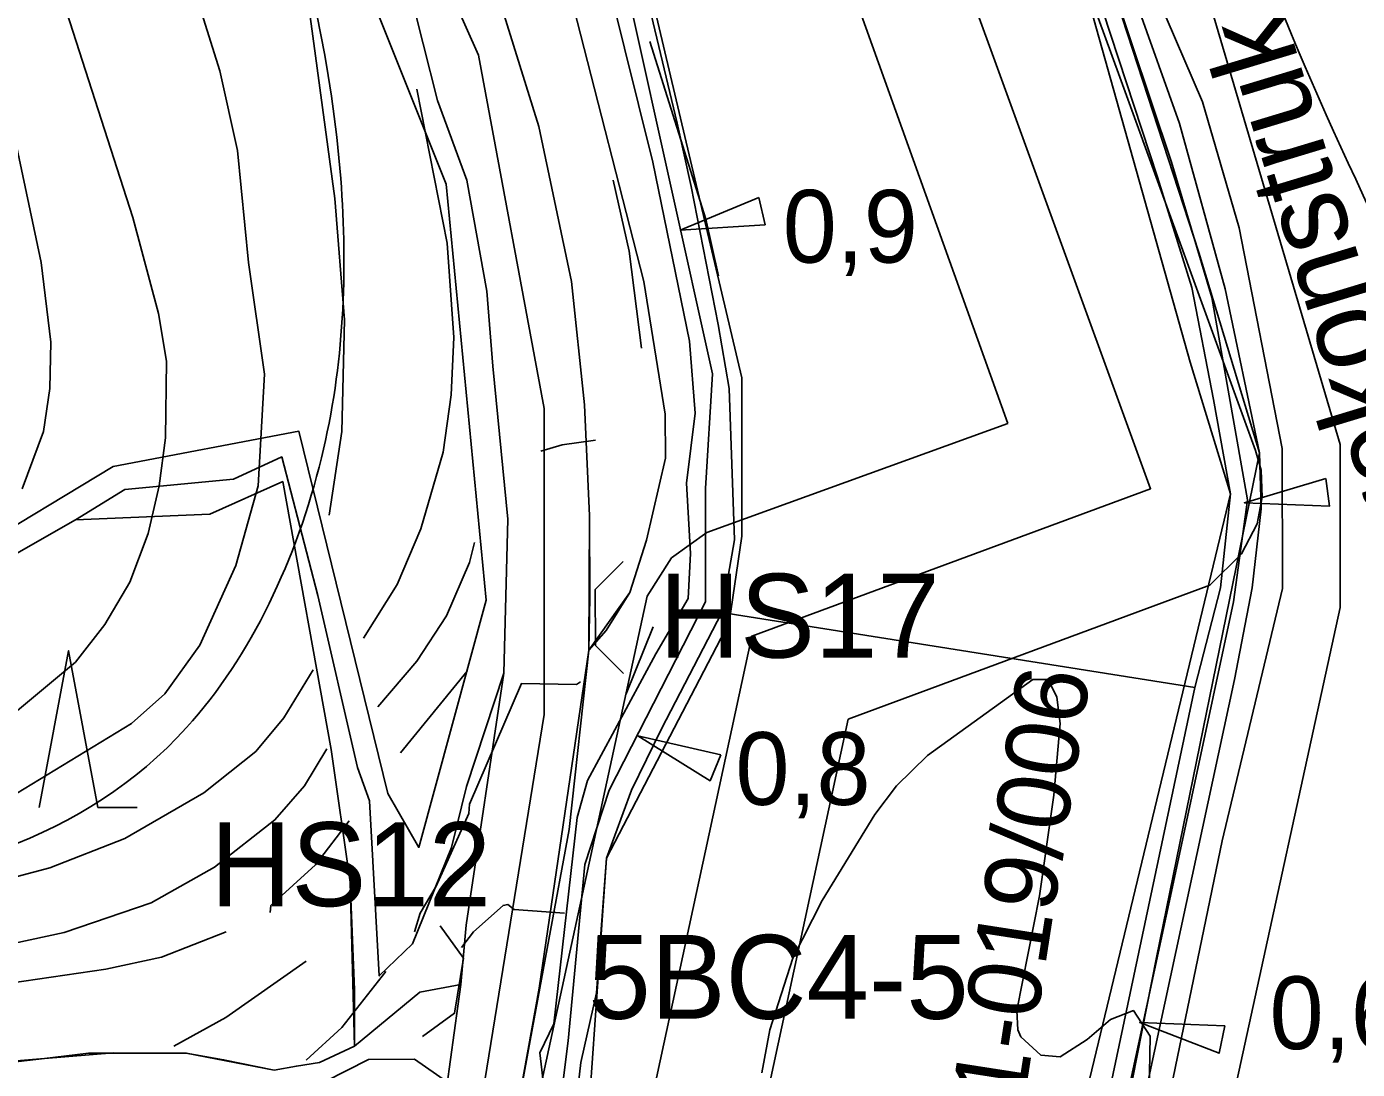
# Model space of a CAD drawing. Extents: x -684583 to -680383, y -1157874 to -1154904.
# Drawn here: x -683125.8 to -682887.9, y -1157689.5 to -1157503 of the extents above; entities that cross this region are included whole.
import ezdxf

# ---------------------------------------------------------------- set-up
doc = ezdxf.new("R2010")
doc.units = 0
for name, color, linetype in [('01_DOPRAVA', 7, 'Continuous'), ('01_OBVOD PÚ', 7, 'Continuous'), ('01_PRVKY PRŮZKUMU', 7, 'Continuous'), ('01_PRVKY PSZ', 7, 'Continuous'), ('01_SPRÁV_HRANICE', 7, 'Continuous'), ('01_VRSTEVNICE', 7, 'Continuous'), ('02_KULTURY STAV', 7, 'Continuous'), ('03_PC_OBJEKTY_STAV', 7, 'Continuous'), ('03_PC_STAV', 7, 'Continuous'), ('04_ZPF_OP_ORGAN', 7, 'Continuous'), ('05_VHO_V_TOK', 7, 'Continuous'), ('06_BIOGEOGRAFIE', 7, 'Continuous'), ('06_ÚSES_BC', 7, 'Continuous'), ('06_ÚSES_IP', 7, 'Continuous'), ('07_OCH_P A POPISY TI', 7, 'Continuous'), ('07_PLYNOVOD', 7, 'Continuous')]:
    doc.layers.add(name, color=color, linetype=linetype)

msp = doc.modelspace()

# ---------------------------------------------------------------- linework, layer by layer
at = {"layer": '01_DOPRAVA'}
msp.add_lwpolyline([(-683054.51, -1157758.92), (-683045.66, -1157702.14), (-683033.32, -1157625.99), (-683033.32, -1157571.3), (-683045.07, -1157508.09), (-683105.62, -1157372.25), (-683148.82, -1157294.04), (-683163.81, -1157254.05), (-683168.81, -1157196.71), (-683165.28, -1157159.67), (-683135.89, -1157075.28), (-683079.46, -1156981.49), (-683035.96, -1156902.98), (-682993.94, -1156817.72), (-682972.78, -1156716.87), (-682952.5, -1156631.31), (-682921.05, -1156497.23), (-682883.43, -1156372.57), (-682870.79, -1156344.34), (-682802.61, -1156200.56), (-682782.62, -1156147.93)], dxfattribs=at)
at = {"layer": '01_OBVOD PÚ'}
msp.add_lwpolyline([(-682865.53, -1157341.29), (-682893.56, -1157332.68), (-682915.26, -1157330.93), (-682949.07, -1157325.62), (-682955.11, -1157345.57), (-682959.54, -1157356.74), (-682962.28, -1157384.25), (-682960.41, -1157397.25), (-682935.1, -1157471.19), (-682915.62, -1157516.47), (-682909.09, -1157538.97), (-682901.39, -1157578.47), (-682901.33, -1157603.49), (-682912.12, -1157648.58), (-682925.59, -1157713.72), (-682932.97, -1157763.18), (-682930, -1157800.25), (-682921.17, -1157813.46), (-682989.26, -1157839.49)], dxfattribs=at)
at = {"layer": '01_PRVKY PRŮZKUMU'}
for points in [[(-683025.92, -1157705.32), (-683022.15, -1157651.71), (-683000.24, -1157609.57), (-682997.99, -1157594.15), (-682997.99, -1157565.8), (-683020.17, -1157471.89), (-683050.97, -1157393.39), (-683079.01, -1157360), (-683101.29, -1157316.95)], [(-682879.89, -1157360.72), (-682946.46, -1157363.51), (-682949.54, -1157394.01), (-682938.25, -1157436.4), (-682914.65, -1157497.57), (-682890.98, -1157577.72), (-682890.98, -1157606.89), (-682909.88, -1157693.41)]]:
    msp.add_lwpolyline(points, dxfattribs=at)
at = {"layer": '01_PRVKY PSZ'}
msp.add_lwpolyline([(-682951.59, -1157030.23), (-682949.58, -1157052.3), (-682959.2, -1157265.52), (-682962.61, -1157285.78), (-682967.05, -1157374.21), (-682960.06, -1157422.81), (-682935.41, -1157484.7), (-682916.27, -1157543.42), (-682905.44, -1157579.25), (-682923.84, -1157669.47), (-682932.49, -1157713.29), (-682940.15, -1157759.63), (-682931.41, -1157813.92)], dxfattribs=at)
at = {"layer": '01_SPRÁV_HRANICE'}
msp.add_lwpolyline([(-682865.53, -1157341.29), (-682893.56, -1157332.68), (-682915.26, -1157330.93), (-682949.07, -1157325.62), (-682955.11, -1157345.57), (-682959.54, -1157356.74), (-682962.28, -1157384.25), (-682960.41, -1157397.25), (-682935.1, -1157471.19), (-682915.62, -1157516.47), (-682909.09, -1157538.97), (-682901.39, -1157578.47), (-682901.33, -1157603.49), (-682912.12, -1157648.58), (-682925.59, -1157713.72), (-682932.97, -1157763.18), (-682930, -1157800.25), (-682921.17, -1157813.46), (-682989.26, -1157839.49)], dxfattribs=at)
at = {"layer": '01_VRSTEVNICE'}
for points in [[(-683136.36, -1157347.17), (-683133.65, -1157353.16), (-683120.24, -1157376.84), (-683111.97, -1157392.82), (-683097.42, -1157424.77), (-683087.72, -1157450.73), (-683080.59, -1157475.55), (-683075.17, -1157501.23), (-683070.74, -1157533.75), (-683069.03, -1157555.43), (-683069.46, -1157575.4), (-683071.74, -1157590.38)], [(-683127.66, -1157640.16), (-683107.12, -1157627.61), (-683101.13, -1157622.33), (-683094.85, -1157613.63), (-683088.43, -1157599.37), (-683084.44, -1157585.1), (-683083.3, -1157565.13), (-683086.15, -1157545.16), (-683088.15, -1157525.19), (-683091.29, -1157510.93), (-683094.85, -1157499.52), (-683102.98, -1157479.54), (-683118.1, -1157436.75), (-683128.94, -1157409.08)], [(-683127.8, -1157625.61), (-683117.1, -1157616.63), (-683111.83, -1157609.92), (-683107.41, -1157602.36), (-683104.12, -1157593.66), (-683102.13, -1157585.1), (-683100.99, -1157576.54), (-683100.84, -1157562.85), (-683102.27, -1157554.29), (-683106.83, -1157537.17), (-683119.24, -1157498.66), (-683131.37, -1157455.87)], [(-683014.4, -1157505.65), (-683004.42, -1157537.46), (-683002.13, -1157547.59)], [(-683056.05, -1157514.21), (-683050.63, -1157541.74), (-683049.49, -1157558.57), (-683049.92, -1157568.84), (-683051.35, -1157579.11), (-683055.34, -1157592.8), (-683059.62, -1157602.79), (-683065.61, -1157612.35)], [(-683128.09, -1157522.34), (-683123.24, -1157545.16), (-683121.53, -1157559.43), (-683121.67, -1157567.7), (-683122.81, -1157575.4), (-683126.66, -1157585.67)], [(-683015.9, -1157560.51), (-683018.11, -1157543.16), (-683020.96, -1157530.47)], [(-683033.91, -1157578.93), (-683030.1, -1157577.8), (-683024.13, -1157576.98)], [(-683045.78, -1157595.23), (-683046.64, -1157598.8), (-683050.78, -1157608.35), (-683056.05, -1157616.48), (-683063.04, -1157624.61)], [(-683013.83, -1157610.35), (-683018.68, -1157622.33)], [(-683159.47, -1157661.56), (-683142.21, -1157658.85), (-683121.67, -1157653.43), (-683108.26, -1157648.15), (-683094.14, -1157640.02), (-683084.87, -1157632.6), (-683079.87, -1157626.59), (-683074.6, -1157618.05)], [(-683059.01, -1157632.86), (-683047.07, -1157618.25)], [(-683056.48, -1157664.84), (-683055.48, -1157661.56), (-683052.63, -1157656.71), (-683046.78, -1157643.73), (-683046.64, -1157642.02), (-683037.37, -1157620.48), (-683027.52, -1157620.62), (-683026.81, -1157620.19)], [(-682925.52, -1157713.39), (-682924.96, -1157683.53), (-682927.96, -1157678.96), (-682932.09, -1157680.53), (-682936.23, -1157684.1), (-682941.08, -1157687.23), (-682944.5, -1157686.95), (-682948.07, -1157683.67), (-682948.64, -1157682.38), (-682948.79, -1157678.96), (-682944.79, -1157658.42), (-682942.22, -1157640.45), (-682941.08, -1157627.61), (-682941.65, -1157622.9), (-682943.22, -1157619.76), (-682945.93, -1157619.76), (-682964.76, -1157633.32), (-682970.32, -1157638.74), (-682974.17, -1157643.87), (-682983.59, -1157659.28), (-682988.87, -1157669.55), (-682993, -1157682.38), (-682994.43, -1157690.09)], [(-683337.78, -1157704.35), (-683318.09, -1157695.65), (-683309.1, -1157692.8), (-683302.26, -1157691.37), (-683282.57, -1157689.38), (-683275.44, -1157689.52), (-683240.92, -1157686.09), (-683219.52, -1157681.81), (-683210.68, -1157679.25), (-683179.87, -1157672.26), (-683171.17, -1157671.12), (-683145.35, -1157669.4), (-683128.23, -1157666.98), (-683119.1, -1157664.98), (-683103.55, -1157659.71), (-683092.28, -1157653.28), (-683081.44, -1157644.87), (-683076.17, -1157638.74), (-683072.17, -1157632.17)], [(-683082.3, -1157661.42), (-683082.16, -1157660.13), (-683074.17, -1157652.86), (-683068.18, -1157645.01)], [(-683029.66, -1157661.56), (-683038.65, -1157660.85), (-683039.79, -1157659.99), (-683040.65, -1157660.13), (-683045.92, -1157664.84), (-683048.07, -1157667.69)], [(-683224.66, -1157694.51), (-683216.67, -1157691.23), (-683180.15, -1157681.53), (-683111.68, -1157671.54), (-683101.7, -1157669.4), (-683090.15, -1157664.84)], [(-683099.5, -1157685.31), (-683090.24, -1157680.17), (-683075.88, -1157670.12)], [(-683061.62, -1157671.97), (-683069.46, -1157681.96), (-683075.88, -1157687.81)]]:
    msp.add_lwpolyline(points, dxfattribs=at)
at = {"layer": '02_KULTURY STAV'}
for points in [[(-683033.42, -1157692.12), (-683034.08, -1157686.53), (-683031.58, -1157681.33), (-683027.44, -1157644.4), (-683025.58, -1157637.78), (-683013.37, -1157615.15), (-683007.58, -1157605.24), (-683007.18, -1157597.21), (-683007.87, -1157584.65), (-683006.31, -1157572.11), (-683007.34, -1157559.25), (-683013.9, -1157527.23), (-683021.51, -1157496.5), (-683027.43, -1157474.84), (-683031.55, -1157461.02), (-683044.3, -1157425.6), (-683054.13, -1157403.28), (-683058.47, -1157396.94), (-683070.54, -1157382.77), (-683080.89, -1157368.49), (-683092.7, -1157351.15), (-683100.09, -1157338.35), (-683104.91, -1157328.42), (-683109.86, -1157316.49)], [(-683123.39, -1157320.54), (-683093.3, -1157375.73), (-683088.54, -1157377.96), (-683076.17, -1157387.28), (-683062.38, -1157405.88), (-683055.9, -1157423.11), (-683052.29, -1157436.79), (-683041.28, -1157465.46), (-683028.05, -1157499.48), (-683015.51, -1157548.59), (-683011.68, -1157572.3), (-683011.64, -1157580.2), (-683015.05, -1157594.84), (-683018, -1157604.18), (-683025.32, -1157614.52), (-683034.2, -1157674.95), (-683041.64, -1157716.25)], [(-682925.59, -1157713.72), (-682912.12, -1157648.58), (-682901.33, -1157603.49), (-682901.39, -1157578.47), (-682909.09, -1157538.97), (-682915.62, -1157516.47), (-682935.1, -1157471.19)], [(-683016.79, -1157489.83), (-683009.51, -1157520.25), (-683007.03, -1157531.61), (-683002.19, -1157556.27), (-683000.27, -1157567.73), (-682999.3, -1157594.75), (-683001.56, -1157607.79), (-683012.36, -1157628.56), (-683017.73, -1157639.54), (-683022.15, -1157651.71), (-683023.59, -1157670.76), (-683023.97, -1157675.79), (-683026.76, -1157688.24), (-683028.56, -1157703.91)], [(-683052.69, -1157706.77), (-683048.74, -1157678.14), (-683048.22, -1157674.26), (-683047.26, -1157663.68), (-683040.52, -1157618.63), (-683039.8, -1157591.06), (-683042.49, -1157563.72), (-683043.54, -1157550.33), (-683047.17, -1157530.46), (-683052.37, -1157516.21), (-683057.49, -1157495.91), (-683043.34, -1157491.71), (-683034.27, -1157520.87), (-683028.44, -1157548.59), (-683026.1, -1157570.61), (-683025.21, -1157590.49), (-683025.32, -1157614.52), (-683034.2, -1157674.95), (-683041.64, -1157716.25)], [(-683033.42, -1157692.12), (-683034.08, -1157686.53), (-683031.58, -1157681.33), (-683027.44, -1157644.4), (-683025.58, -1157637.78), (-683013.37, -1157615.15), (-683007.58, -1157605.24), (-683007.18, -1157597.21), (-683007.87, -1157584.65), (-683006.31, -1157572.11), (-683007.34, -1157559.25), (-683013.9, -1157527.23), (-683021.51, -1157496.5)], [(-682927.4, -1157498.74), (-682919.76, -1157520.36), (-682911.54, -1157549.91), (-682905.44, -1157579.25), (-682905.14, -1157589.23), (-682906.77, -1157603.34), (-682909.9, -1157619.72), (-682927.09, -1157699.5)], [(-682927.09, -1157699.5), (-682909.9, -1157619.72), (-682906.77, -1157603.34), (-682905.14, -1157589.23), (-682905.44, -1157579.25), (-682911.54, -1157549.91), (-682919.76, -1157520.36), (-682927.4, -1157498.74)], [(-682933.41, -1157500.16), (-682923.67, -1157529.91), (-682917.54, -1157549.63), (-682913.64, -1157569.71), (-682910.6, -1157586.57), (-682912.42, -1157603.36), (-682917.01, -1157621.2), (-682932.27, -1157693.31)], [(-683128.09, -1157597.48), (-683117.09, -1157591.23), (-683093.1, -1157590.19), (-683080.04, -1157584.35), (-683071.41, -1157632.26), (-683067.97, -1157656), (-683067.24, -1157685.33), (-683073.47, -1157688.22), (-683077.6, -1157688.87), (-683081.6, -1157689.6), (-683090.63, -1157687.74), (-683097.29, -1157686.54), (-683114.77, -1157686.54), (-683122.62, -1157687.52), (-683133.39, -1157688.42)], [(-682932.27, -1157693.31), (-682917.01, -1157621.2), (-683001.56, -1157607.79), (-683012.36, -1157628.56), (-683017.73, -1157639.54), (-683022.15, -1157651.71), (-683023.59, -1157670.76), (-683023.97, -1157675.79), (-683026.76, -1157688.24), (-683028.56, -1157703.91)], [(-683123.59, -1157642.62), (-683118.34, -1157614.62), (-683113.09, -1157642.62), (-683106.09, -1157642.62)], [(-683155.61, -1157697), (-683139.21, -1157689.44), (-683122.62, -1157687.52), (-683110.28, -1157686.5), (-683097.29, -1157686.54), (-683081.6, -1157689.6), (-683077.6, -1157688.87), (-683073.47, -1157688.22), (-683067.24, -1157685.33), (-683055.55, -1157675.64), (-683048.22, -1157674.26), (-683048.74, -1157678.14), (-683052.69, -1157706.77)]]:
    msp.add_lwpolyline(points, dxfattribs=at)
for points in [[(-683050.32, -1157398.08), (-683047.27, -1157404.35), (-683041.25, -1157416.74), (-683026.4, -1157458.67), (-683016.79, -1157489.83), (-683009.51, -1157520.25), (-683007.03, -1157531.61), (-683002.19, -1157556.27), (-683000.27, -1157567.73), (-682999.3, -1157594.75), (-683001.56, -1157607.79), (-682917.01, -1157621.2), (-682912.42, -1157603.36), (-682910.6, -1157586.57), (-682913.64, -1157569.71), (-682917.54, -1157549.63), (-682923.67, -1157529.91), (-682933.41, -1157500.16), (-682952.33, -1157451.75), (-682962.44, -1157424.45), (-682967.7, -1157402.05), (-682969.62, -1157390.02), (-682970.5, -1157367.3)], [(-683093.3, -1157375.73), (-683088.54, -1157377.96), (-683076.17, -1157387.28), (-683062.38, -1157405.88), (-683055.9, -1157423.11), (-683052.29, -1157436.79), (-683041.28, -1157465.46), (-683028.05, -1157499.48), (-683015.51, -1157548.59), (-683011.68, -1157572.3), (-683011.64, -1157580.2), (-683015.05, -1157594.84), (-683018, -1157604.18), (-683022.23, -1157611), (-683025.32, -1157614.52), (-683025.15, -1157605.08), (-683025.21, -1157590.49), (-683026.1, -1157570.61), (-683028.44, -1157548.59), (-683034.27, -1157520.87), (-683043.34, -1157491.71), (-683064.17, -1157440.15), (-683079.83, -1157403.21)], [(-683117.09, -1157591.23), (-683108.26, -1157585.78), (-683088.84, -1157583.9), (-683080.23, -1157579.96), (-683073.77, -1157604.75), (-683066.67, -1157635.47), (-683064.53, -1157641.47), (-683062.79, -1157672.74), (-683056.86, -1157667.01), (-683049.9, -1157649.8), (-683047.18, -1157638.86), (-683040.52, -1157618.63), (-683047.26, -1157663.68), (-683048.22, -1157674.26), (-683055.55, -1157675.64), (-683067.24, -1157685.33), (-683067.23, -1157675.25), (-683067.97, -1157656), (-683071.41, -1157632.26), (-683080.04, -1157584.35), (-683093.1, -1157590.19)]]:
    msp.add_lwpolyline(points, close=True, dxfattribs=at)
at = {"layer": '03_PC_OBJEKTY_STAV'}
for points in [[(-683019.11, -1157618.66), (-683024.13, -1157613.68), (-683024.17, -1157603.68), (-683019.19, -1157598.66)], [(-683051.89, -1157663.82), (-683047.74, -1157669.55), (-683049.32, -1157679.42), (-683055.05, -1157683.57)]]:
    msp.add_lwpolyline(points, dxfattribs=at)
at = {"layer": '03_PC_STAV'}
msp.add_lwpolyline([(-682956.44, -1157024.49), (-682963.29, -1157054.08), (-682959.47, -1157076.95), (-682964.05, -1157160.08), (-682974.97, -1157364.97), (-682973.09, -1157394), (-682966.3, -1157425.87), (-682936.61, -1157496.14), (-682917.8, -1157562.99), (-682910.6, -1157586.57), (-682939.66, -1157707.13), (-682946.26, -1157762.29), (-682942.96, -1157791.01), (-682939.8, -1157807.76), (-682935.77, -1157818.43)], dxfattribs=at)
at = {"layer": '04_ZPF_OP_ORGAN'}
msp.add_lwpolyline([(-683343.12, -1157216.48), (-683255.77, -1157147.12), (-683212.14, -1157111.99), (-683188, -1157100.46), (-683171.81, -1157095.24), (-683160.28, -1157100.46), (-683176.2, -1157149.05), (-683182.23, -1157222.89), (-683169.61, -1157275.32), (-683083.46, -1157449.64), (-683050.81, -1157531.17), (-683043.68, -1157605.57), (-683055.75, -1157649.76), (-683061.24, -1157640.16), (-683077.15, -1157575.37), (-683110.35, -1157581.68), (-683135.87, -1157597.03), (-683152.6, -1157616.55), (-683323.54, -1157289.05), (-683339.45, -1157238.26)], close=True, dxfattribs=at)
at = {"layer": '05_VHO_V_TOK'}
for points in [[(-683104.4, -1157320.5), (-683087.93, -1157352.63), (-683056.41, -1157394.83), (-683048.58, -1157408.35), (-683030.22, -1157456.96), (-683017.89, -1157499.04), (-683003.2, -1157565.08), (-683004.5, -1157585.59), (-683004.5, -1157605.86), (-683021.68, -1157639.53), (-683026.07, -1157652.81), (-683029.03, -1157684.34), (-683031.64, -1157705.21), (-683039.46, -1157727.73), (-683041.71, -1157740.42), (-683039.58, -1157758.56), (-683025.24, -1157783.93), (-683011.26, -1157822.58), (-683004.38, -1157828.62), (-682987.38, -1157838.7)], [(-682965.51, -1157340.18), (-682965.51, -1157340.18), (-682965.51, -1157360.81), (-682967.05, -1157374.21), (-682965.75, -1157391.04), (-682960.06, -1157422.81), (-682952.71, -1157444.51), (-682935.41, -1157484.7), (-682921.19, -1157527.26), (-682913.96, -1157551.44), (-682907.56, -1157587.6), (-682910.05, -1157605.86), (-682921.19, -1157657.67), (-682931.03, -1157703.43), (-682937.07, -1157743.15), (-682940.15, -1157759.63), (-682933.52, -1157806.34), (-682930.91, -1157816.77)]]:
    msp.add_lwpolyline(points, dxfattribs=at)
for points in [[(-682994.95, -1157533.56), (-682993.81, -1157538.43), (-683008.98, -1157539.41)], [(-682893.56, -1157583.82), (-682892.94, -1157588.78), (-682908.13, -1157588.15)], [(-683001.75, -1157633.21), (-683003.65, -1157637.84), (-683016.58, -1157629.84)], [(-682911.64, -1157681.68), (-682912.67, -1157686.57), (-682926.84, -1157681.05)]]:
    msp.add_lwpolyline(points, close=True, dxfattribs=at)
at = {"layer": '06_BIOGEOGRAFIE'}
for points in [[(-683662.04, -1156787.77), (-683658.6, -1156877.34), (-683631.05, -1156927.29), (-683541.5, -1156975.52), (-683489.85, -1157028.92), (-683414.08, -1157027.2), (-683362.42, -1157025.48), (-683360.7, -1157063.37), (-683464.02, -1157132.27), (-683493.29, -1157163.28), (-683474.35, -1157189.11), (-683407.19, -1157171.89), (-683317.65, -1157115.05), (-683269.44, -1157104.71), (-683207.44, -1157173.61), (-683186.78, -1157259.74), (-683105.85, -1157416.48), (-683069.69, -1157530.17), (-683073.13, -1157580.12), (-683097.24, -1157628.35), (-683264.27, -1157657.63), (-683431.3, -1157647.3), (-683531.17, -1157605.96), (-683636.21, -1157542.23), (-683651.71, -1157521.56), (-683682.7, -1157519.83), (-683708.53, -1157528.45), (-683818.74, -1157547.39), (-683870.4, -1157518.11), (-683980.6, -1157521.56), (-684052.92, -1157490.55), (-684171.74, -1157400.98), (-684213.07, -1157375.14), (-684250.95, -1157388.92), (-684249.23, -1157437.15), (-684237.17, -1157466.44), (-684170.02, -1157518.11), (-684097.7, -1157562.9), (-684011.6, -1157605.96), (-683953.05, -1157602.51), (-683891.06, -1157626.63), (-683835.96, -1157619.74), (-683789.47, -1157599.07), (-683713.7, -1157578.4), (-683625.88, -1157592.18), (-683551.84, -1157667.97), (-683445.07, -1157736.87), (-683346.92, -1157771.32), (-683179.89, -1157767.87), (-683081.74, -1157773.04), (-683016.71, -1157810.65), (-682999.16, -1157844)], [(-682391.66, -1157338.99), (-682455.37, -1157402.72), (-682453.65, -1157490.57), (-682474.31, -1157533.63), (-682517.36, -1157516.41), (-682548.36, -1157480.24), (-682624.12, -1157464.73), (-682725.72, -1157421.67), (-682779.1, -1157392.39), (-682861.75, -1157359.66), (-682903.08, -1157387.22), (-682911.69, -1157468.18), (-682873.81, -1157562.92), (-682861.75, -1157654.21), (-682892.75, -1157709.33), (-682894.47, -1157790.29), (-682823.43, -1157844.83)]]:
    msp.add_spline(points, degree=3, dxfattribs=at)
at = {"layer": '06_ÚSES_BC'}
msp.add_lwpolyline([(-683041.64, -1157716.25), (-683036.1, -1157685.93), (-683028.82, -1157646.6), (-683025.32, -1157614.52), (-683025.21, -1157590.49), (-683026.1, -1157570.61), (-683028.44, -1157548.59), (-683034.27, -1157520.87), (-683043.34, -1157491.71)], dxfattribs=at)
at = {"layer": '06_ÚSES_IP'}
msp.add_lwpolyline([(-683072.48, -1157691.63), (-683064.7, -1157687.69), (-683056.49, -1157687.64), (-683050.62, -1157691.77)], dxfattribs=at)
at = {"layer": '07_OCH_P A POPISY TI'}
for p, q in [((-682930.42, -1157512.04), (-682963.96, -1157419.76)), ((-683004.12, -1157424.22), (-682950.45, -1157573.95)), ((-682906.12, -1157578.8), (-682930.42, -1157512.04)), ((-682950.45, -1157573.95), (-683004.24, -1157593.49)), ((-682905.15, -1157582.3), (-682906.12, -1157578.8)), ((-682904.93, -1157587.14), (-682905.15, -1157582.3)), ((-682905.87, -1157591.89), (-682904.93, -1157587.14)), ((-682908.63, -1157597.27), (-682905.87, -1157591.89)), ((-683004.24, -1157593.49), (-683010.55, -1157598.02)), ((-682914.32, -1157602.9), (-682908.63, -1157597.27)), ((-683010.55, -1157598.02), (-683014.92, -1157604.85)), ((-682978.95, -1157626.86), (-682914.32, -1157602.9)), ((-683014.92, -1157604.85), (-683042.79, -1157733.09)), ((-683006.5, -1157754.54), (-682978.95, -1157626.86))]:
    msp.add_line(p, q, dxfattribs=at)
at = {"layer": '07_PLYNOVOD'}
msp.add_lwpolyline([(-682369.73, -1156748.62), (-682856.97, -1157005.33), (-682893.69, -1157072.4), (-682917.2, -1157156.56), (-682941.77, -1157266.45), (-682978.36, -1157266.27), (-682983.87, -1157423.53), (-682924.91, -1157585.64), (-682996.21, -1157612), (-683026.05, -1157750.31), (-683062.69, -1157756.02), (-683074.55, -1157765.36), (-683106.38, -1157774.6)], dxfattribs=at)

# ---------------------------------------------------------------- texts
at = {"layer": '01_PRVKY PSZ'}
msp.add_text('rekonstrukce OP3', height=15, rotation=106.8571, dxfattribs=at).set_placement((-682874.09, -1157589.03))
at = {"layer": '03_PC_OBJEKTY_STAV'}
for s, p in [('HS17', (-683012.77, -1157615.84)), ('HS12', (-683092.98, -1157660.28))]:
    msp.add_text(s, height=15, dxfattribs=at).set_placement(p)
at = {"layer": '05_VHO_V_TOK'}
for s, p in [('0,9', (-682990.67, -1157545.21)), ('0,8', (-682999.13, -1157642.17)), ('0,6', (-682903.63, -1157685.84))]:
    msp.add_text(s, height=13, dxfattribs=at).set_placement(p)
msp.add_text('4-14-01-019/006', height=13, rotation=81.1659, dxfattribs=at).set_placement((-682955.35, -1157745.77))
at = {"layer": '06_BIOGEOGRAFIE'}
msp.add_text('5BC4-5', height=15, dxfattribs=at).set_placement((-683025.43, -1157680.42))

doc.saveas('drawing.dxf')
